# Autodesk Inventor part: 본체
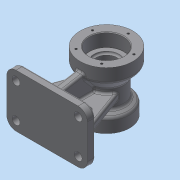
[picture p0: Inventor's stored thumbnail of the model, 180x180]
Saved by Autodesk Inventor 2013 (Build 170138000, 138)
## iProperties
Created: 2015-08
Part Number: 본체
Material: 일반
Document SubType Name: Modeling
Designer: Administrator
Density: 1 g/cm^3
Author: Administrator
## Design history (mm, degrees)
sketch "스케치2"
  geometry: L1 (0, 0)-(0, -90); L2 (0, 0)-(40, 0); L3 (35, -90)-(0, -90); L4 (40, 0)-(40, -20); L5 (40, -20)-(26, -36.685); L6 (26, -36.685)-(26, -64.804); L7 (26, -64.804)-(35, -70); L8 (35, -70)-(35, -90)
  constraints: 16 end point, 3 perpendicular, 2 parallel, 1 vertical
  dimensions: "d0" = 90 distance of L1.start L1.end; "d2" = 40 deg angle of L6 L5; "d3" = 60 deg angle of L6 L7; "d4" = 20 distance of L2.end L4.end; "d5" = 20 distance of L7.end L3.start; "d6" = 80 diameter of L4 L1; "d7" = 70 diameter of L8 L1; "d8" = 52 diameter of L6 L1
revolve "회전1" sketch "스케치2" stored, may be unused: angle "d9" = 90 deg
node "작업 평면1"
sketch "스케치3"
  geometry: L1 (61, -90)-(-61, -90); L2 (-61, -90)-(-61, -10); L3 (-61, -10)-(61, -10); L4 (61, -10)-(61, -90); L5 (-35, -90)-(35, -90) reference; L6 (-35, -70)-(35, -70) reference; 2 further points
  constraints: 8 end point, 2 midpoint, 2 parallel, 1 horizontal, 1 perpendicular
  dimensions: "d11" = 122 distance of L1.start L1.end; "d13" = 80 distance of L1.end L2.end
extrude "돌출1" join sketch "스케치3" distance "d14" = 12; taper "d15" = 0 deg
fillet "모깎기1" dims "d16" = 14
node "작업 평면2"
sketch "스케치5"
  geometry: L1 (61, -90)-(-61, -90) reference; L2 (-61, -90)-(-61, -78) reference; L3 (-61, -78)-(61, -78) reference; L4 (61, -78)-(61, -90) reference; L5 (-51, -78)-(-25.091, -6.815); L6 (25.091, -6.815)-(51, -78); A1 r 26 centre (0, 0) between (-25.091, -6.815) and (25.091, -6.815) reference; 1 further point
  constraints: 4 end point, 2 point on circle, 2 point on line
  dimensions: "d18" = 10 distance of L5.start L2.end; "d19" = 10 distance of L3.end L6.end; "d20" = 70 deg angle of L3 L6; "d22" = 70 deg angle of L3 L5
extrude "돌출2" join sketch "스케치5" stored distance "d23" = 12; taper "d24" = 0 deg
sketch "스케치6"
  geometry: L1 (-40, 0)-(40, 0) reference; L2 (40, 0)-(40, -20) reference; L3 (40, -20)-(26, -36.685) reference; L4 (26, -36.685)-(26, -64.804) reference; L5 (26, -64.804)-(35, -70) reference; L6 (35, -70)-(35, -90) reference; L7 (35, -90)-(-35, -90) reference; L8 (-35, -90)-(-35, -70) reference; L9 (-35, -70)-(-26, -64.804) reference; L10 (-26, -64.804)-(-26, -56) reference; L11 (-26, -56)-(-78, -56) reference; L12 (-78, -56)-(-78, -90) reference; L13 (-78, -90)-(-90, -90) reference; L14 (-90, -90)-(-90, -10) reference; L15 (-90, -10)-(-78, -10) reference; L16 (-78, -10)-(-78, -44) reference; L17 (-78, -44)-(-26, -44) reference; L18 (-26, -44)-(-26, -36.685) reference; L19 (-26, -36.685)-(-40, -20) reference; L20 (-40, -20)-(-40, 0) reference; L21 (-35, -80)-(-78, -80); L22 (-78, -20)-(-40, -13.3); 1 further point
  constraints: 4 end point, 3 point on line, 1 midpoint, 1 perpendicular
  dimensions: "d25" = 10 distance between parallel lines of L13 L21; "d26" = 10 distance of L15.end L22.start; "d27" = 80 deg angle of L16 L22
  node "절단 모서리 투영3"
feature "리브1" dims "d28" = 1, "d29" = 12, "d30" = 0, "d31" = 0, "d32" = 1, "d33" = 1
feature "리브2" dims "d34" = 1, "d35" = 12, "d36" = 0, "d37" = 0, "d38" = 1, "d39" = 1
hole "구멍1" diameter "d42" = 38; stored, may be unused: countersink angle "d46" = 90 deg, drill point angle "d48" = 0 deg; dims "d40" = 10, "d41" = 10, "d43" = 6, "d44" = 52, "d45" = 20, "d47" = 23
sketch "스케치7"
  geometry: C1 r 35 at (0, 0) reference; 1 further point
  constraints: 1 coincident
hole "구멍2" sketch "스케치7" at (0, 0) diameter "d49" = 32; stored, may be unused: countersink angle "d53" = 90 deg, drill point angle "d55" = 0 deg; dims "d50" = 6, "d51" = 40, "d52" = 17, "d54" = 23
fillet "모깎기2" dims "d56" = 0.3
fillet "모깎기3" dims "d57" = 3
chamfer "모따기1" distance "d58" = 1; stored, may be unused: second distance "d59" = 2, angle "d60" = 45 deg
sketch "스케치8" dims "d61" = 54
  geometry: C1 r 21 at (0, 0) reference; 2 further points
  constraints: 2 vertical alignment, 1 coincident, 2 other
hole "구멍3" sketch "스케치8" at (0, 27) diameter "d62" = 3.242; stored, may be unused: countersink angle "d66" = 90 deg, drill point angle "d68" = 118 deg; dims "d63" = 10, "d64" = 40, "d65" = 17, "d67" = 13
sketch "스케치9" dims "d72" = 66
  geometry: C1 r 27 at (0, 0) reference; 2 further points
  constraints: 2 vertical alignment, 1 coincident, 2 other
hole "구멍4" sketch "스케치9" at (0, 33) diameter "d73" = 3.242; stored, may be unused: countersink angle "d77" = 90 deg, drill point angle "d79" = 118 deg; dims "d74" = 10, "d75" = 40, "d76" = 17, "d78" = 13
sketch "스케치10"
  geometry: A1 r 14 centre (-47, 76) between (-47, 90) and (-61, 76) reference; A2 r 14 centre (-47, 24) between (-61, 24) and (-47, 10) reference; A3 r 14 centre (47, 24) between (47, 10) and (61, 24) reference; A4 r 14 centre (47, 76) between (61, 76) and (47, 90) reference; 5 further points
  constraints: 4 coincident
hole "구멍5" sketch "스케치10" at (-47, 76), (47, 76), (47, 24), (-47, 24) diameter "d83" = 12; stored, may be unused: countersink angle "d87" = 90 deg, drill point angle "d89" = 118 deg; dims "d84" = 10, "d85" = 40, "d86" = 17, "d88" = 13
sketch "스케치11"
  geometry: L1 (-6, -78)-(-51, -78) reference; L2 (-30, -54)-(-30, -60); L3 (-18, -54)-(-18, -60); A1 r 26 centre (0, 0) between (-25.091, -6.815) and (-6, -25.298) reference; A2 r 6 centre (-24, -54) between (-18, -54) and (-30, -54); A3 r 6 centre (-24, -60) between (-30, -60) and (-18, -60)
  constraints: 4 end point, 4 point on circle, 4 tangent, 2 centre point, 1 vertical alignment
  dimensions: "d90" = 12 diameter of A2; "d91" = 12 diameter of A3; "d92" = 18 dimension on A3 A2; "d93" = 18 distance from line of A3.centre L1; "d94" = 24 horizontal distance of A1.centre A2.centre
extrude "돌출3" cut sketch "스케치11" stored distance "d95" = 12; taper "d96" = 0 deg
fillet "모깎기4" dims "d97" = 3
fillet "모깎기5" dims "d98" = 3
fillet "모깎기6" dims "d99" = 5
fillet "모깎기7" dims "d100" = 3
fillet "모깎기8" dims "d101" = 3
sketch "스케치12"
  geometry: L1 (-10, -41.081)-(1, -41.081) reference; L2 (-3, -0.963)-(-3, -38.081) reference; 2 further points
  constraints: 1 other
  dimensions: "d102" = 24 distance from line of L1 point (13, -17.081); "d103" = 16 distance from line of point (13, -17.081) L2
feature "엠보싱1" sketch "스케치12" dims "d0" = 90, "d2" = 40 deg, "d3" = 60 deg, "d4" = 20, "d5" = 20, "d6" = 80, "d7" = 70, "d8" = 52, "d104" = 0.5, "d105" = 0
node "솔리드1"
pattern_circular "원형 패턴1" dims angle "d70" = 360 deg
pattern_circular "원형 패턴2" dims angle "d81" = 360 deg
mirror "대칭1"
node "투영된 루프1"
node "절단 모서리 투영2"
